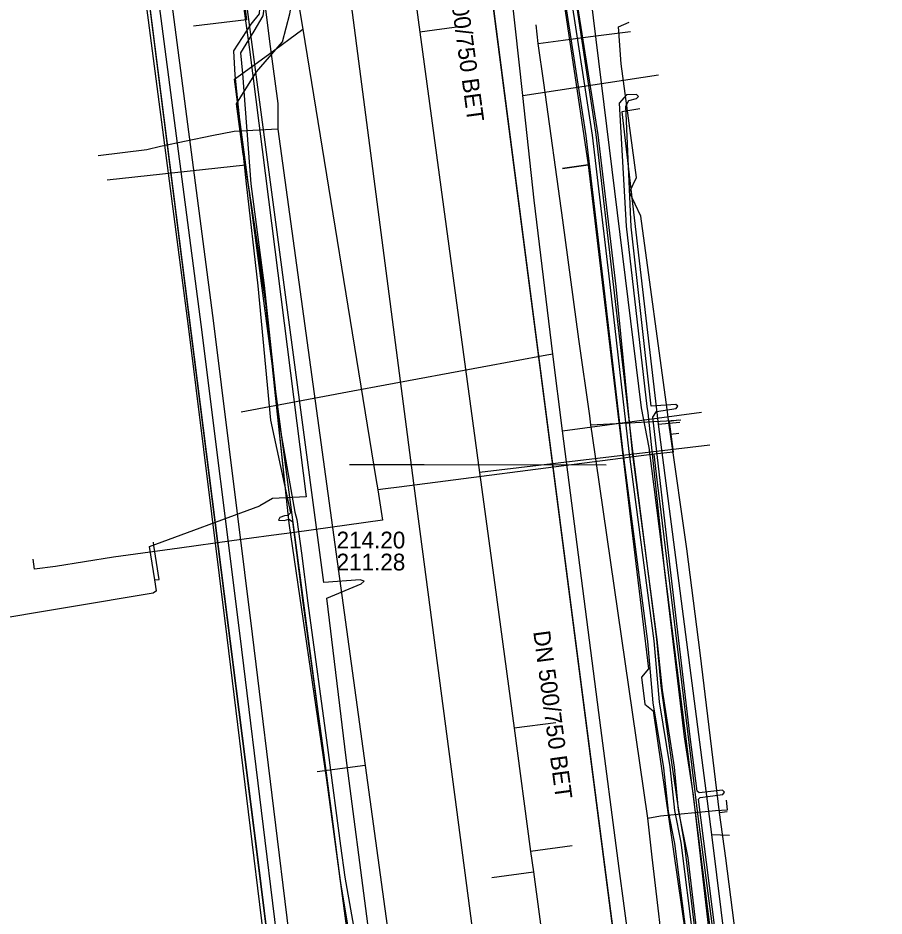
# Model space of a CAD drawing. Extents: x -600309 to -598967, y -1161267 to -1160292.
# Drawn here: x -599114.07 to -599072.82, y -1160844.91 to -1160802.1 of the extents above; entities that cross this region are included whole.
import ezdxf

# ---------------------------------------------------------------- set-up
doc = ezdxf.new("R2010")
doc.units = 0
for name, color, linetype in [('Vrstva 10', 7, 'Continuous'), ('Vrstva 12', 7, 'Continuous'), ('Vrstva 13', 7, 'Continuous'), ('Vrstva 16', 7, 'Continuous'), ('Vrstva 19', 7, 'Continuous'), ('Vrstva 25', 7, 'Continuous'), ('Vrstva 26', 7, 'Continuous'), ('Vrstva 30', 7, 'Continuous'), ('Vrstva 37', 7, 'Continuous'), ('Vrstva 42', 7, 'Continuous'), ('Vrstva 43', 7, 'Continuous'), ('Vrstva 44', 7, 'Continuous'), ('Vrstva 54', 7, 'Continuous'), ('Vrstva 55', 7, 'Continuous'), ('Vrstva 58', 7, 'Continuous'), ('Vrstva 9', 7, 'Continuous')]:
    doc.layers.add(name, color=color, linetype=linetype)

msp = doc.modelspace()

# ---------------------------------------------------------------- linework, layer by layer
at = {"layer": 'Vrstva 10'}
msp.add_lwpolyline([(-599092.52, -1160793.12), (-599092.45, -1160793.67), (-599081.91, -1160875.07), (-599081.84, -1160875.63)], dxfattribs=at)
at = {"layer": 'Vrstva 12'}
for points in [[(-599108.23, -1160764.95), (-599107.21, -1160772.31), (-599105.81, -1160782.49), (-599105.41, -1160786.51), (-599103.04, -1160803.6), (-599100.35, -1160824.93), (-599101.95, -1160825), (-599102.56, -1160825.35)], [(-599092.52, -1160793.12), (-599092.45, -1160793.67), (-599081.91, -1160875.07), (-599081.84, -1160875.63)], [(-599101.15, -1160797.38), (-599100.85, -1160800.53), (-599100.51, -1160802.64)], [(-599102.14, -1160803.84), (-599100.51, -1160802.64)], [(-599100.51, -1160802.64), (-599097.03, -1160824.06)], [(-599100.91, -1160826.62), (-599103.76, -1160805.02), (-599102.14, -1160803.84)], [(-599084.45, -1160806.43), (-599085.31, -1160806.57), (-599083.58, -1160821.47)], [(-599082.6, -1160821.27), (-599083.05, -1160821.33), (-599082.86, -1160822.79), (-599083.77, -1160822.9)], [(-599083.58, -1160821.47), (-599082.55, -1160821.36)], [(-599083.58, -1160821.47), (-599081.04, -1160841.02)], [(-599085.87, -1160823.17), (-599095.92, -1160824.46)], [(-599083.77, -1160822.9), (-599085.87, -1160823.17)], [(-599083.63, -1160824.12), (-599083.77, -1160822.9)], [(-599097.03, -1160824.06), (-599096.94, -1160824.59)], [(-599095.92, -1160824.46), (-599096.57, -1160824.54)], [(-599083.44, -1160825.66), (-599083.63, -1160824.12)], [(-599096.94, -1160824.59), (-599096.71, -1160826.04), (-599100.91, -1160826.62)], [(-599096.57, -1160824.54), (-599096.94, -1160824.59)], [(-599107.56, -1160828.89), (-599107.81, -1160827.29), (-599102.56, -1160825.35)], [(-599076.63, -1160878.9), (-599081.68, -1160840.17), (-599083.44, -1160825.66)], [(-599100.91, -1160826.62), (-599102.01, -1160826.77)], [(-599088.96, -1160928.6), (-599088.56, -1160920.13), (-599096.87, -1160857.22), (-599097.65, -1160851.27), (-599100.91, -1160826.62)], [(-599107.6, -1160827.24), (-599107.62, -1160827.09)], [(-599103.89, -1160827.02), (-599106.38, -1160827.37)], [(-599102.01, -1160826.77), (-599103.89, -1160827.02)], [(-599106.38, -1160827.37), (-599109.53, -1160827.8), (-599112.28, -1160828.25), (-599113.28, -1160828.38), (-599113.35, -1160827.89)], [(-599107.56, -1160828.89), (-599107.35, -1160828.87), (-599107.6, -1160827.24)], [(-599107.48, -1160829.41), (-599107.56, -1160828.89)], [(-599107.48, -1160829.41), (-599107.63, -1160829.52), (-599123.97, -1160832.25), (-599123.67, -1160842.23), (-599123.59, -1160843.68)], [(-599081.04, -1160841.02), (-599080.18, -1160841.05)], [(-599081.04, -1160841.02), (-599080.8, -1160842.95)], [(-599080.8, -1160842.95), (-599078.46, -1160861.8)]]:
    msp.add_lwpolyline(points, dxfattribs=at)
at = {"layer": 'Vrstva 13'}
for p, q in [((-599090.023, -1160805.797), (-599083.566, -1160804.809)), ((-599088.14, -1160821.78), (-599081.52, -1160820.895))]:
    msp.add_line(p, q, dxfattribs=at)
for points in [[(-599075.9, -1160931.24), (-599079.535, -1160887.787), (-599079.91, -1160883.306), (-599080.64, -1160873.22), (-599081.78, -1160870.95), (-599082.322, -1160866.755), (-599083.4, -1160858.2), (-599083.77, -1160855.1), (-599085.43, -1160842.642), (-599086.4, -1160835.21), (-599088.14, -1160821.78), (-599088.595, -1160818.123), (-599089.48, -1160810.78), (-599090.023, -1160805.797), (-599090.75, -1160799.13), (-599091.65, -1160790.55), (-599092.81, -1160787.13), (-599093.61, -1160780.55)], [(-599088.595, -1160818.123), (-599088.885, -1160818.18), (-599098.124, -1160819.896), (-599103.437, -1160820.897)]]:
    msp.add_lwpolyline(points, dxfattribs=at)
at = {"layer": 'Vrstva 16'}
for points in [[(-599111.49, -1160733.02), (-599103, -1160796), (-599102.06, -1160803.46), (-599101.69, -1160806.18), (-599101.7, -1160807.4), (-599097.54, -1160837.73), (-599093.02, -1160870.62), (-599087.04, -1160918.94), (-599088.54, -1160938.31), (-599089.97, -1160951.28), (-599094.48, -1160985.82)], [(-599101.7, -1160807.4), (-599103.78, -1160807.51), (-599104.84, -1160807.72), (-599107.29, -1160808.22), (-599107.94, -1160808.39), (-599110.25, -1160808.67)], [(-599097.54, -1160837.73), (-599099.83, -1160838.04)]]:
    msp.add_lwpolyline(points, dxfattribs=at)
at = {"layer": 'Vrstva 19'}
for points in [[(-599084.92, -1160929.7), (-599084.859, -1160929.27), (-599083.83, -1160922.03), (-599083.57, -1160912.78), (-599095.07, -1160825.37), (-599102.5, -1160768.3), (-599104.6, -1160752.25), (-599109.62, -1160709.21), (-599119.67, -1160628.93), (-599126.32, -1160575.37), (-599128.11, -1160560.16), (-599133.16, -1160522.31), (-599135.34, -1160510.45), (-599143.35, -1160452.12)], [(-599074.12, -1160920.92), (-599077.86, -1160888.45), (-599077.9, -1160888.08), (-599078.12, -1160886.29), (-599078.87, -1160879.81), (-599078.95, -1160879.15), (-599079.09, -1160878.06), (-599081.55, -1160861.2), (-599081.63, -1160860.81), (-599081.71, -1160860.16), (-599082.39, -1160854.73), (-599082.5, -1160853.73), (-599083.86, -1160842.11), (-599084.08, -1160840.25), (-599084.26, -1160838.93), (-599086.72, -1160821.9), (-599086.78, -1160821.49), (-599086.83, -1160821.07), (-599087.36, -1160817.41), (-599088.12, -1160811.74), (-599089.02, -1160805.19), (-599089.3, -1160803.31), (-599089.39, -1160802.42)], [(-599089.3, -1160803.31), (-599088.11, -1160803.15), (-599086.8, -1160802.98), (-599084.9, -1160802.74)], [(-599086.78, -1160821.49), (-599085.58, -1160821.43), (-599083.19, -1160821.3), (-599082.5, -1160821.26)], [(-599084.08, -1160840.25), (-599083.47, -1160840.14), (-599080.85, -1160839.88), (-599080.28, -1160839.84), (-599080.32, -1160839.39)]]:
    msp.add_lwpolyline(points, dxfattribs=at)
at = {"layer": 'Vrstva 25'}
msp.add_lwpolyline([(-599143.178, -1160720.938), (-599141.755, -1160734.053), (-599138.218, -1160760.282), (-599112.94, -1160757.829), (-599111.463, -1160769.37), (-599107.708, -1160798.709), (-599105.356, -1160816.718), (-599103.51, -1160831.548), (-599102.32, -1160841.304), (-599101.225, -1160850.266), (-599100.484, -1160856.31), (-599099.868, -1160862.22), (-599099.247, -1160868.108), (-599098.443, -1160877.321), (-599097.727, -1160886.173), (-599097.266, -1160892.101), (-599096.454, -1160904.425), (-599095.969, -1160912.721), (-599095.595, -1160919.034), (-599103.507, -1160920.005), (-599104.146, -1160921.035)], dxfattribs=at)
at = {"layer": 'Vrstva 26'}
for points in [[(-599142.581, -1160720.874), (-599141.159, -1160733.981), (-599137.701, -1160759.629), (-599112.418, -1160757.175), (-599110.868, -1160769.293), (-599107.113, -1160798.632), (-599104.76, -1160816.642), (-599102.914, -1160831.475), (-599101.724, -1160841.231), (-599100.629, -1160850.193), (-599099.888, -1160856.242), (-599099.271, -1160862.158), (-599098.65, -1160868.051), (-599097.845, -1160877.271), (-599097.129, -1160886.126), (-599096.667, -1160892.058), (-599095.855, -1160904.388), (-599095.37, -1160912.686), (-599094.962, -1160919.561), (-599103.149, -1160920.566), (-599103.636, -1160921.351)], [(-599104.656, -1160920.719), (-599103.866, -1160919.445), (-599096.227, -1160918.508), (-599096.568, -1160912.757), (-599097.053, -1160904.463), (-599097.864, -1160892.144), (-599098.326, -1160886.221), (-599099.041, -1160877.371), (-599099.845, -1160868.166), (-599100.465, -1160862.283), (-599101.08, -1160856.377), (-599101.82, -1160850.339), (-599102.915, -1160841.377), (-599104.105, -1160831.622), (-599105.951, -1160816.794), (-599108.303, -1160798.785), (-599112.058, -1160769.446), (-599113.461, -1160758.482), (-599138.735, -1160760.935), (-599142.35, -1160734.125), (-599143.774, -1160721.003)]]:
    msp.add_lwpolyline(points, dxfattribs=at)
at = {"layer": 'Vrstva 30'}
msp.add_lwpolyline([(-599106.401, -1160797.69), (-599103.788, -1160797.368), (-599103.195, -1160802.181), (-599105.719, -1160802.492)], dxfattribs=at)
at = {"layer": 'Vrstva 37'}
msp.add_lwpolyline([(-599145.199, -1160718.091), (-599144.973, -1160720.636), (-599143.638, -1160720.873), (-599142.218, -1160733.982), (-599138.62, -1160760.741), (-599113.361, -1160758.301), (-599110.558, -1160779.77), (-599102.688, -1160841.965), (-599100.671, -1160858.294), (-599099.28, -1160872.901), (-599097.781, -1160890.694), (-599096.04, -1160918.702), (-599103.803, -1160919.551), (-599124.155, -1160954.441), (-599136.613, -1160975.097), (-599143.954, -1160975.244), (-599143.72, -1160985.73), (-599139.675, -1160986.235), (-599125.642, -1160988.682), (-599125.313, -1160988.905), (-599117.843, -1160990.212), (-599113.154, -1161007.176), (-599114.51, -1161007.627)], dxfattribs=at)
at = {"layer": 'Vrstva 42'}
for points in [[(-599145.2, -1160718.09), (-599144.97, -1160720.64), (-599143.64, -1160720.87), (-599142.22, -1160733.98), (-599138.62, -1160760.74), (-599113.36, -1160758.3), (-599110.56, -1160779.77), (-599102.69, -1160841.97), (-599100.67, -1160858.29), (-599099.28, -1160872.9), (-599097.78, -1160890.69), (-599096.04, -1160918.7), (-599103.8, -1160919.55), (-599124.15, -1160954.44), (-599136.61, -1160975.1), (-599143.95, -1160975.24), (-599143.72, -1160985.73), (-599139.67, -1160986.24), (-599125.64, -1160988.68), (-599125.31, -1160988.91), (-599117.84, -1160990.21), (-599113.15, -1161007.18), (-599114.51, -1161007.63)], [(-599074.316, -1160904.716), (-599074.708, -1160898.099), (-599076.903, -1160883.36), (-599077.625, -1160877.494), (-599077.776, -1160876.14), (-599079.881, -1160861.221), (-599079.911, -1160858.123), (-599080.513, -1160855.626), (-599081.205, -1160850.723), (-599082.318, -1160841.429), (-599082.618, -1160839.774), (-599082.919, -1160837.699), (-599083.431, -1160833.939), (-599083.641, -1160831.713), (-599084.784, -1160822.749), (-599085.687, -1160814.929), (-599086.529, -1160807.649), (-599087.882, -1160798.625), (-599088.634, -1160791.587), (-599091.432, -1160770.922)], [(-599107.81, -1160774.88), (-599106.89, -1160780.62), (-599106.07, -1160786.68), (-599105.33, -1160792.18), (-599105.01, -1160794.61), (-599104.63, -1160795.7), (-599103.74, -1160796.94), (-599103.28, -1160797.28), (-599103.05, -1160797.73), (-599102.56, -1160801.39), (-599102.59, -1160801.9), (-599102.98, -1160802.39), (-599103.8, -1160803.66), (-599103.75, -1160804.82), (-599103.2, -1160810), (-599102.65, -1160814.87), (-599102.04, -1160821.27), (-599101.1, -1160825.69), (-599101.22, -1160825.81), (-599101.374, -1160825.836), (-599101.601, -1160825.908), (-599101.672, -1160826.036)], [(-599107.61, -1160774.92), (-599106.59, -1160780.59), (-599105.8, -1160786.67), (-599105.11, -1160792.09), (-599104.71, -1160794.58), (-599104.31, -1160795.65), (-599103.63, -1160796.6), (-599103.23, -1160796.82), (-599102.74, -1160797.69), (-599102.32, -1160801.31), (-599102.41, -1160802), (-599102.84, -1160802.73), (-599103.48, -1160803.76), (-599103.38, -1160804.74), (-599102.99, -1160810), (-599102.35, -1160814.85), (-599101.66, -1160821.24), (-599100.88, -1160825.66), (-599100.79, -1160826.01), (-599100.576, -1160827.617)], [(-599090.679, -1160779.99), (-599089.959, -1160785.37), (-599089.139, -1160791.727), (-599088.419, -1160798.659), (-599087.029, -1160807.72), (-599086.169, -1160814.977), (-599085.269, -1160822.798), (-599084.089, -1160831.816), (-599083.829, -1160834.739), (-599083.329, -1160837.84), (-599083.098, -1160839.923), (-599082.798, -1160841.454), (-599081.619, -1160850.779), (-599080.998, -1160855.715), (-599080.376, -1160858.212), (-599080.33, -1160861.181), (-599078.308, -1160876.17), (-599078.078, -1160877.54), (-599077.359, -1160883.47), (-599075.219, -1160898.176), (-599074.81, -1160904.729)], [(-599090.679, -1160779.99), (-599089.959, -1160785.37), (-599089.139, -1160791.727), (-599088.419, -1160798.659), (-599087.029, -1160807.72), (-599086.169, -1160814.977), (-599085.269, -1160822.798), (-599084.089, -1160831.816), (-599083.829, -1160834.739), (-599083.329, -1160837.84), (-599083.098, -1160839.923), (-599082.798, -1160841.454), (-599081.619, -1160850.779), (-599080.998, -1160855.715), (-599080.376, -1160858.212), (-599080.33, -1160861.181), (-599078.308, -1160876.17), (-599078.078, -1160877.54), (-599077.359, -1160883.47), (-599075.219, -1160898.176), (-599074.81, -1160904.729)], [(-599090.381, -1160779.95), (-599089.661, -1160785.33), (-599088.841, -1160791.693), (-599088.121, -1160798.621), (-599086.731, -1160807.68), (-599085.871, -1160814.943), (-599084.971, -1160822.762), (-599083.791, -1160831.784), (-599083.531, -1160834.701), (-599083.031, -1160837.8), (-599082.802, -1160839.877), (-599082.502, -1160841.406), (-599081.321, -1160850.741), (-599080.702, -1160855.659), (-599080.076, -1160858.172), (-599080.03, -1160861.159), (-599078.012, -1160876.126), (-599077.782, -1160877.498), (-599077.061, -1160883.43), (-599074.921, -1160898.144), (-599074.51, -1160904.711)], [(-599090.381, -1160779.95), (-599089.661, -1160785.33), (-599088.841, -1160791.693), (-599088.121, -1160798.621), (-599086.731, -1160807.68), (-599085.871, -1160814.943), (-599084.971, -1160822.762), (-599083.791, -1160831.784), (-599083.531, -1160834.701), (-599083.031, -1160837.8), (-599082.802, -1160839.877), (-599082.502, -1160841.406), (-599081.321, -1160850.741), (-599080.702, -1160855.659), (-599080.076, -1160858.172), (-599080.03, -1160861.159), (-599078.012, -1160876.126), (-599077.782, -1160877.498), (-599077.061, -1160883.43), (-599074.921, -1160898.144), (-599074.51, -1160904.711)], [(-599089.959, -1160785.37), (-599089.139, -1160791.727), (-599088.419, -1160798.659), (-599087.029, -1160807.72), (-599086.169, -1160814.977), (-599085.269, -1160822.798), (-599084.089, -1160831.816), (-599083.829, -1160834.739), (-599083.329, -1160837.84), (-599083.098, -1160839.923), (-599082.798, -1160841.454), (-599081.619, -1160850.779), (-599080.998, -1160855.715), (-599080.376, -1160858.212), (-599080.33, -1160861.181), (-599078.308, -1160876.17), (-599078.078, -1160877.54), (-599077.359, -1160883.47), (-599075.219, -1160898.176), (-599074.81, -1160904.729)], [(-599089.959, -1160785.37), (-599089.139, -1160791.727), (-599088.419, -1160798.659), (-599087.029, -1160807.72), (-599086.169, -1160814.977), (-599085.269, -1160822.798), (-599084.089, -1160831.816), (-599083.829, -1160834.739), (-599083.329, -1160837.84), (-599083.098, -1160839.923), (-599082.798, -1160841.454), (-599081.619, -1160850.779), (-599080.998, -1160855.715), (-599080.376, -1160858.212), (-599080.33, -1160861.181), (-599078.308, -1160876.17), (-599078.078, -1160877.54), (-599077.359, -1160883.47), (-599075.219, -1160898.176), (-599074.81, -1160904.729)], [(-599089.661, -1160785.33), (-599088.841, -1160791.693), (-599088.121, -1160798.621), (-599086.731, -1160807.68), (-599085.871, -1160814.943), (-599084.971, -1160822.762), (-599083.791, -1160831.784), (-599083.531, -1160834.701), (-599083.031, -1160837.8), (-599082.802, -1160839.877), (-599082.502, -1160841.406), (-599081.321, -1160850.741), (-599080.702, -1160855.659), (-599080.076, -1160858.172), (-599080.03, -1160861.159), (-599078.012, -1160876.126), (-599077.782, -1160877.498), (-599077.061, -1160883.43), (-599074.921, -1160898.144), (-599074.51, -1160904.711)], [(-599089.661, -1160785.33), (-599088.841, -1160791.693), (-599088.121, -1160798.621), (-599086.731, -1160807.68), (-599085.871, -1160814.943), (-599084.971, -1160822.762), (-599083.791, -1160831.784), (-599083.531, -1160834.701), (-599083.031, -1160837.8), (-599082.802, -1160839.877), (-599082.502, -1160841.406), (-599081.321, -1160850.741), (-599080.702, -1160855.659), (-599080.076, -1160858.172), (-599080.03, -1160861.159), (-599078.012, -1160876.126), (-599077.782, -1160877.498), (-599077.061, -1160883.43), (-599074.921, -1160898.144), (-599074.51, -1160904.711)], [(-599080.76, -1160846.47), (-599081.66, -1160839.33), (-599081.576, -1160839.26), (-599080.5, -1160839.112), (-599080.414, -1160839.002), (-599080.517, -1160838.915), (-599081.627, -1160839.043), (-599081.72, -1160838.96), (-599082.06, -1160836.37), (-599082.99, -1160828.41), (-599083.84, -1160821.13), (-599083.66, -1160820.86), (-599082.715, -1160820.721), (-599082.642, -1160820.611), (-599082.742, -1160820.528), (-599083.69, -1160820.59), (-599083.91, -1160820.609), (-599084.87, -1160812.06), (-599085.12, -1160806.31), (-599084.97, -1160806.03), (-599084.605, -1160805.946), (-599084.521, -1160805.847), (-599084.619, -1160805.753), (-599085.09, -1160805.76), (-599085.43, -1160806.16), (-599085.1, -1160812.03), (-599084.114, -1160820.621), (-599084.07, -1160820.92), (-599083.28, -1160828.48), (-599082.34, -1160836.36), (-599081.91, -1160839.14), (-599081.07, -1160846.45)], [(-599101.672, -1160826.036), (-599101.401, -1160826.054), (-599101.17, -1160825.99), (-599100.99, -1160826.1), (-599100.5, -1160829.96), (-599099.52, -1160837.13), (-599099.08, -1160840.518)], [(-599100.576, -1160827.617), (-599100.26, -1160829.99), (-599099.3, -1160837.12), (-599098.71, -1160841.557)], [(-599099.08, -1160840.518), (-599098.74, -1160843.13), (-599097.39, -1160851.27), (-599096.83, -1160856.87), (-599096.32, -1160860.8), (-599095.2, -1160863.38), (-599094.63, -1160869.56), (-599094.223, -1160873.894), (-599094.22, -1160873.93), (-599094.24, -1160874.07), (-599094.236, -1160874.1), (-599093.79, -1160877.9), (-599093.03, -1160884.11), (-599092.58, -1160888.9), (-599091.95, -1160894.11), (-599090.84, -1160902.9), (-599090.07, -1160909.46)], [(-599098.71, -1160841.557), (-599098.51, -1160843.06), (-599097.06, -1160851.23), (-599096.6, -1160856.83), (-599095.99, -1160860.77), (-599094.84, -1160863.26), (-599094.33, -1160869.53)]]:
    msp.add_lwpolyline(points, dxfattribs=at)
at = {"layer": 'Vrstva 43'}
msp.add_lwpolyline([(-599096.69, -1160858.19), (-599099.37, -1160838.41), (-599101.15, -1160826.18), (-599102.35, -1160814.95), (-599103.24, -1160809.11), (-599103.34, -1160808.59), (-599103.66, -1160806.2), (-599103.26, -1160805.52), (-599102.71, -1160804.67), (-599101.48, -1160803.24), (-599101.12, -1160801.91), (-599100.94, -1160800.83), (-599101.22, -1160799.78), (-599101.59, -1160798.25), (-599102.41, -1160797.18), (-599103.12, -1160796.39), (-599104.66, -1160795.31), (-599105.06, -1160794.78), (-599105.18, -1160794.29), (-599105.95, -1160788.44), (-599106.05, -1160787.88), (-599106.72, -1160781.72), (-599106.77, -1160781.39), (-599107.74, -1160774.58)], dxfattribs=at)
at = {"layer": 'Vrstva 44'}
msp.add_lwpolyline([(-599112.09, -1160608.13), (-599111.98, -1160609.99), (-599109.504, -1160629.736), (-599106.065, -1160655.324), (-599103.642, -1160674.134), (-599100.509, -1160697.439), (-599095.391, -1160735.084), (-599093.34, -1160750.202), (-599089.712, -1160777.364), (-599087.879, -1160792.317), (-599087.434, -1160795.875), (-599084.392, -1160820.684), (-599084.024, -1160822.578), (-599080.74, -1160848.464), (-599078.594, -1160865.22), (-599075.405, -1160890.518), (-599073.694, -1160908.257), (-599072.822, -1160913.918)], dxfattribs=at)
at = {"layer": 'Vrstva 54'}
for points in [[(-599098.28, -1160823.38), (-599094.73, -1160823.39)], [(-599094.73, -1160823.39), (-599086.06, -1160823.4)]]:
    msp.add_lwpolyline(points, dxfattribs=at)
at = {"layer": 'Vrstva 55'}
for points in [[(-599092.185, -1160769.424), (-599090.543, -1160781.503), (-599090.964, -1160782.029), (-599090.81, -1160783.276), (-599090.235, -1160783.738), (-599089.189, -1160791.733), (-599088.468, -1160798.666), (-599086.92, -1160809.103), (-599088.13, -1160809.27), (-599086.92, -1160809.103), (-599086.219, -1160814.983), (-599085.556, -1160820.57), (-599084.041, -1160833.123), (-599084.373, -1160833.528), (-599084.219, -1160834.816), (-599083.815, -1160835.132), (-599082.09, -1160847.11)], [(-599089.74, -1160904.2), (-599095.28, -1160861.65), (-599093.168, -1160861.165), (-599093.01, -1160861.04), (-599093.198, -1160860.967), (-599095.34, -1160861.11), (-599098.44, -1160837.37), (-599099.36, -1160829.75), (-599097.727, -1160829.077), (-599097.58, -1160828.94), (-599097.773, -1160828.883), (-599099.5, -1160829.01), (-599104.74, -1160789.64), (-599102.93, -1160789.467), (-599102.67, -1160789.34), (-599102.847, -1160789.243), (-599104.81, -1160789.12), (-599106.54, -1160777.46)]]:
    msp.add_lwpolyline(points, dxfattribs=at)
at = {"layer": 'Vrstva 58'}
for points in [[(-599086.86, -1161033.06), (-599078.59, -1160971.02), (-599078.49, -1160969.9), (-599076.14, -1160921.39), (-599076.18, -1160920.27), (-599081.77, -1160876.19), (-599081.84, -1160875.63), (-599081.91, -1160875.07), (-599089.2, -1160818.766), (-599092.45, -1160793.67), (-599092.6, -1160792.56), (-599099.731, -1160739.009)], [(-599086.86, -1161033.06), (-599078.59, -1160971.02), (-599078.49, -1160969.9), (-599076.14, -1160921.39), (-599076.18, -1160920.27), (-599081.77, -1160876.19), (-599081.84, -1160875.63), (-599081.91, -1160875.07), (-599089.2, -1160818.766), (-599092.45, -1160793.67), (-599092.6, -1160792.56), (-599099.731, -1160739.009)], [(-599086.86, -1161033.06), (-599078.59, -1160971.02), (-599078.49, -1160969.9), (-599076.14, -1160921.39), (-599076.18, -1160920.27), (-599081.77, -1160876.19), (-599081.84, -1160875.63), (-599081.91, -1160875.07), (-599089.2, -1160818.766), (-599092.45, -1160793.67), (-599092.6, -1160792.56), (-599099.731, -1160739.009)], [(-599093.427, -1160756.051), (-599089.92, -1160782.393), (-599088.656, -1160791.731), (-599087.882, -1160798.622), (-599086.454, -1160807.675), (-599085.598, -1160814.893), (-599084.823, -1160822.803), (-599083.641, -1160831.734), (-599083.396, -1160834.139), (-599082.825, -1160837.809), (-599082.621, -1160839.848), (-599082.173, -1160842.132), (-599080.582, -1160855.588), (-599079.808, -1160858.198), (-599079.971, -1160861.216), (-599077.85, -1160876.67), (-599076.872, -1160883.439), (-599074.629, -1160898.16), (-599074.303, -1160904.725)], [(-599103.24, -1160809.11), (-599103.34, -1160808.59), (-599103.66, -1160806.2), (-599102.71, -1160804.67), (-599101.48, -1160803.24), (-599101.12, -1160801.91), (-599100.94, -1160800.83), (-599101.59, -1160798.25), (-599102.41, -1160797.18), (-599103.12, -1160796.39), (-599104.66, -1160795.31), (-599105.06, -1160794.78), (-599105.18, -1160794.29), (-599105.95, -1160788.44), (-599106.05, -1160787.88), (-599106.72, -1160781.72), (-599107.74, -1160774.58)], [(-599096.69, -1160858.19), (-599099.37, -1160838.41), (-599101.15, -1160826.18), (-599102.35, -1160814.95), (-599103.24, -1160809.11), (-599103.34, -1160808.59), (-599103.66, -1160806.2), (-599103.26, -1160805.52), (-599102.71, -1160804.67), (-599101.48, -1160803.24), (-599101.12, -1160801.91), (-599100.94, -1160800.83), (-599101.22, -1160799.78), (-599101.59, -1160798.25), (-599102.41, -1160797.18), (-599103.12, -1160796.39), (-599104.66, -1160795.31), (-599105.06, -1160794.78), (-599105.18, -1160794.29), (-599105.95, -1160788.44), (-599106.05, -1160787.88), (-599106.72, -1160781.72), (-599106.77, -1160781.39), (-599107.74, -1160774.58)], [(-599083, -1160821.94), (-599083.06, -1160821.51), (-599083.15, -1160820.77), (-599084.4, -1160811.54), (-599084.95, -1160810.4), (-599084.62, -1160809.7), (-599085.339, -1160804.281), (-599085.47, -1160802.52), (-599084.963, -1160802.301)], [(-599103.24, -1160809.11), (-599109.826, -1160809.83)], [(-599089.07, -1160922.98), (-599089.182, -1160919.982), (-599089.432, -1160914.988), (-599090.054, -1160909.021), (-599090.98, -1160901.01), (-599091.982, -1160893.138), (-599093.123, -1160884.21), (-599094.365, -1160875.297), (-599096.35, -1160861.06), (-599097.192, -1160854.488), (-599099.37, -1160838.41), (-599101.15, -1160826.18), (-599101.832, -1160819.8), (-599102.257, -1160815.823), (-599103.24, -1160809.11)], [(-599083, -1160821.94), (-599082.59, -1160821.89)], [(-599080.66, -1160839.97), (-599081.583, -1160832.369), (-599082.215, -1160827.409), (-599083, -1160821.94)], [(-599080.66, -1160839.97), (-599080.29, -1160839.93)], [(-599078.24, -1160859.16), (-599078.91, -1160853.43), (-599080.36, -1160842.15), (-599080.66, -1160839.97)]]:
    msp.add_lwpolyline(points, dxfattribs=at)
at = {"layer": 'Vrstva 9'}
for p, q in [((-599092.948, -1160802.502), (-599094.93, -1160802.771)), ((-599081.118, -1160822.468), (-599092.085, -1160823.769)), ((-599088.46, -1160835.693), (-599090.442, -1160835.959)), ((-599087.672, -1160841.56), (-599089.654, -1160841.826)), ((-599091.504, -1160843.073), (-599089.522, -1160842.807))]:
    msp.add_line(p, q, dxfattribs=at)
for points in [[(-599096.7, -1160789.71), (-599096.566, -1160790.701), (-599096.527, -1160790.988), (-599095.937, -1160795.339), (-599094.93, -1160802.771), (-599092.085, -1160823.769), (-599091.36, -1160829.12)], [(-599091.36, -1160829.12), (-599090.442, -1160835.959), (-599089.654, -1160841.826), (-599089.522, -1160842.807), (-599087.834, -1160855.384), (-599087.468, -1160858.11), (-599087.288, -1160859.448), (-599085.647, -1160871.678), (-599085.589, -1160872.104), (-599085.568, -1160872.263), (-599085.39, -1160873.59)]]:
    msp.add_lwpolyline(points, dxfattribs=at)

# ---------------------------------------------------------------- texts
at = {"layer": 'Vrstva 12'}
for rotation, p in [(277.7126, (-599093.742, -1160799.072)), (277.6553, (-599089.533, -1160831.354))]:
    msp.add_text('DN 500/750 BET', height=0.8, rotation=rotation, dxfattribs=at).set_placement(p)
for s, p in [('214.20', (-599098.896, -1160827.386)), ('211.28', (-599098.896, -1160828.436))]:
    msp.add_text(s, height=0.8, dxfattribs=at).set_placement(p)

doc.saveas('drawing.dxf')
